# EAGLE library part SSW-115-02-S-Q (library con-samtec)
THROUGH-HOLE .025" SQ POST SOCKET Source: Samtec SSW.pdf
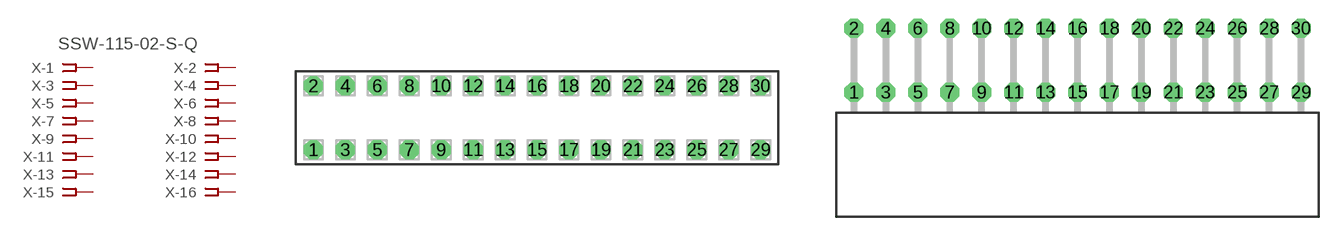
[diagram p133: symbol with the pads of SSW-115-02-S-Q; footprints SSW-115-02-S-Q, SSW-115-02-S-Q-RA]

Designator prefix X; gates -1=FPINV -2=FPIN -3=FPIN -4=FPIN -5=FPIN -6=FPIN -7=FPIN -8=FPIN -9=FPIN -10=FPIN -11=FPIN -12=FPIN -13=FPIN -14=FPIN -15=FPIN -16=FPIN -17=FPIN -18=FPIN -19=FPIN -20=FPIN -21=FPIN -22=FPIN -23=FPIN -24=FPIN -25=FPIN -26=FPIN -27=FPIN -28=FPIN -29=FPIN -30=FPIN

## SSW-115-02-S-Q (MPN: SSW-115-02-S-Q; OC_FARNELL: unknown; OC_NEWARK: 82P6863)  [SSW-115-02-S-Q]
1  -1:1  pas
2  -2:1  pas
3  -3:1  pas
4  -4:1  pas
5  -5:1  pas
6  -6:1  pas
7  -7:1  pas
8  -8:1  pas
9  -9:1  pas
10  -10:1  pas
11  -11:1  pas
12  -12:1  pas
13  -13:1  pas
14  -14:1  pas
15  -15:1  pas
16  -16:1  pas
17  -17:1  pas
18  -18:1  pas
19  -19:1  pas
20  -20:1  pas
21  -21:1  pas
22  -22:1  pas
23  -23:1  pas
24  -24:1  pas
25  -25:1  pas
26  -26:1  pas
27  -27:1  pas
28  -28:1  pas
29  -29:1  pas
30  -30:1  pas

## SSW-115-02-S-QRA (MPN: SSW-115-02-S-Q-RA; OC_FARNELL: unknown; OC_NEWARK: 82P6864)  [SSW-115-02-S-Q-RA]
Pads as for SSW-115-02-S-Q

## Footprint SSW-115-02-S-Q (pad centres in mm)
THROUGH-HOLE .025" SQ POST SOCKET Source: Samtec SSW.pdf
drill 1 pad 1.5 octagon: 1 -17.78,-2.54; 2 -17.78,2.54; 3 -15.24,-2.54; 4 -15.24,2.54; 5 -12.7,-2.54; 6 -12.7,2.54; 7 -10.16,-2.54; 8 -10.16,2.54; 9 -7.62,-2.54; 10 -7.62,2.54; 11 -5.08,-2.54; 12 -5.08,2.54; 13 -2.54,-2.54; 14 -2.54,2.54; 15 0,-2.54; 16 0,2.54; 17 2.54,-2.54; 18 2.54,2.54; 19 5.08,-2.54; 20 5.08,2.54; 21 7.62,-2.54; 22 7.62,2.54; 23 10.16,-2.54; 24 10.16,2.54; 25 12.7,-2.54; 26 12.7,2.54; 27 15.24,-2.54; 28 15.24,2.54; 29 17.78,-2.54; 30 17.78,2.54

## Footprint SSW-115-02-S-Q-RA (pad centres in mm)
THROUGH-HOLE .025" SQ POST SOCKET Source: Samtec SSW.pdf
drill 1 pad 1.5 octagon: 1 -17.78,1.524; 2 -17.78,6.604; 3 -15.24,1.524; 4 -15.24,6.604; 5 -12.7,1.524; 6 -12.7,6.604; 7 -10.16,1.524; 8 -10.16,6.604; 9 -7.62,1.524; 10 -7.62,6.604; 11 -5.08,1.524; 12 -5.08,6.604; 13 -2.54,1.524; 14 -2.54,6.604; 15 0,1.524; 16 0,6.604; 17 2.54,1.524; 18 2.54,6.604; 19 5.08,1.524; 20 5.08,6.604; 21 7.62,1.524; 22 7.62,6.604; 23 10.16,1.524; 24 10.16,6.604; 25 12.7,1.524; 26 12.7,6.604; 27 15.24,1.524; 28 15.24,6.604; 29 17.78,1.524; 30 17.78,6.604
